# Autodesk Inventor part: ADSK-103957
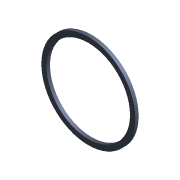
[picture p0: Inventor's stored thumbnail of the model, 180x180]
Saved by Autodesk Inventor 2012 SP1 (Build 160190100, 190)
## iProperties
Shininess: 0.0
Created: 2000-09
Part Number: ADSK-103957
Document SubType Name: Modeling
Stock Number: ADSK-103957
Density: 1 g/cm^3
Material: Default
Density: 0.0
Volumn: 0.0
Area: 0.0
PropertySet Name: Model Information
Control State: 0
Master: False
Checked Out: False
Author: gao
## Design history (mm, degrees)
node "Extrusion1" dims "d2" = 2.5, "d3" = 0
  sketch "Sketch1"
    geometry: C1 r 31 at (-1.003, -0.621); C2 r 34.925 at (-1.003, -0.621)
    constraints: 2 centre point, 1 coincident
    dimensions: "d0" = 62 diameter of C1; "d1" = 69.85 diameter of C2
body "Solid1"
